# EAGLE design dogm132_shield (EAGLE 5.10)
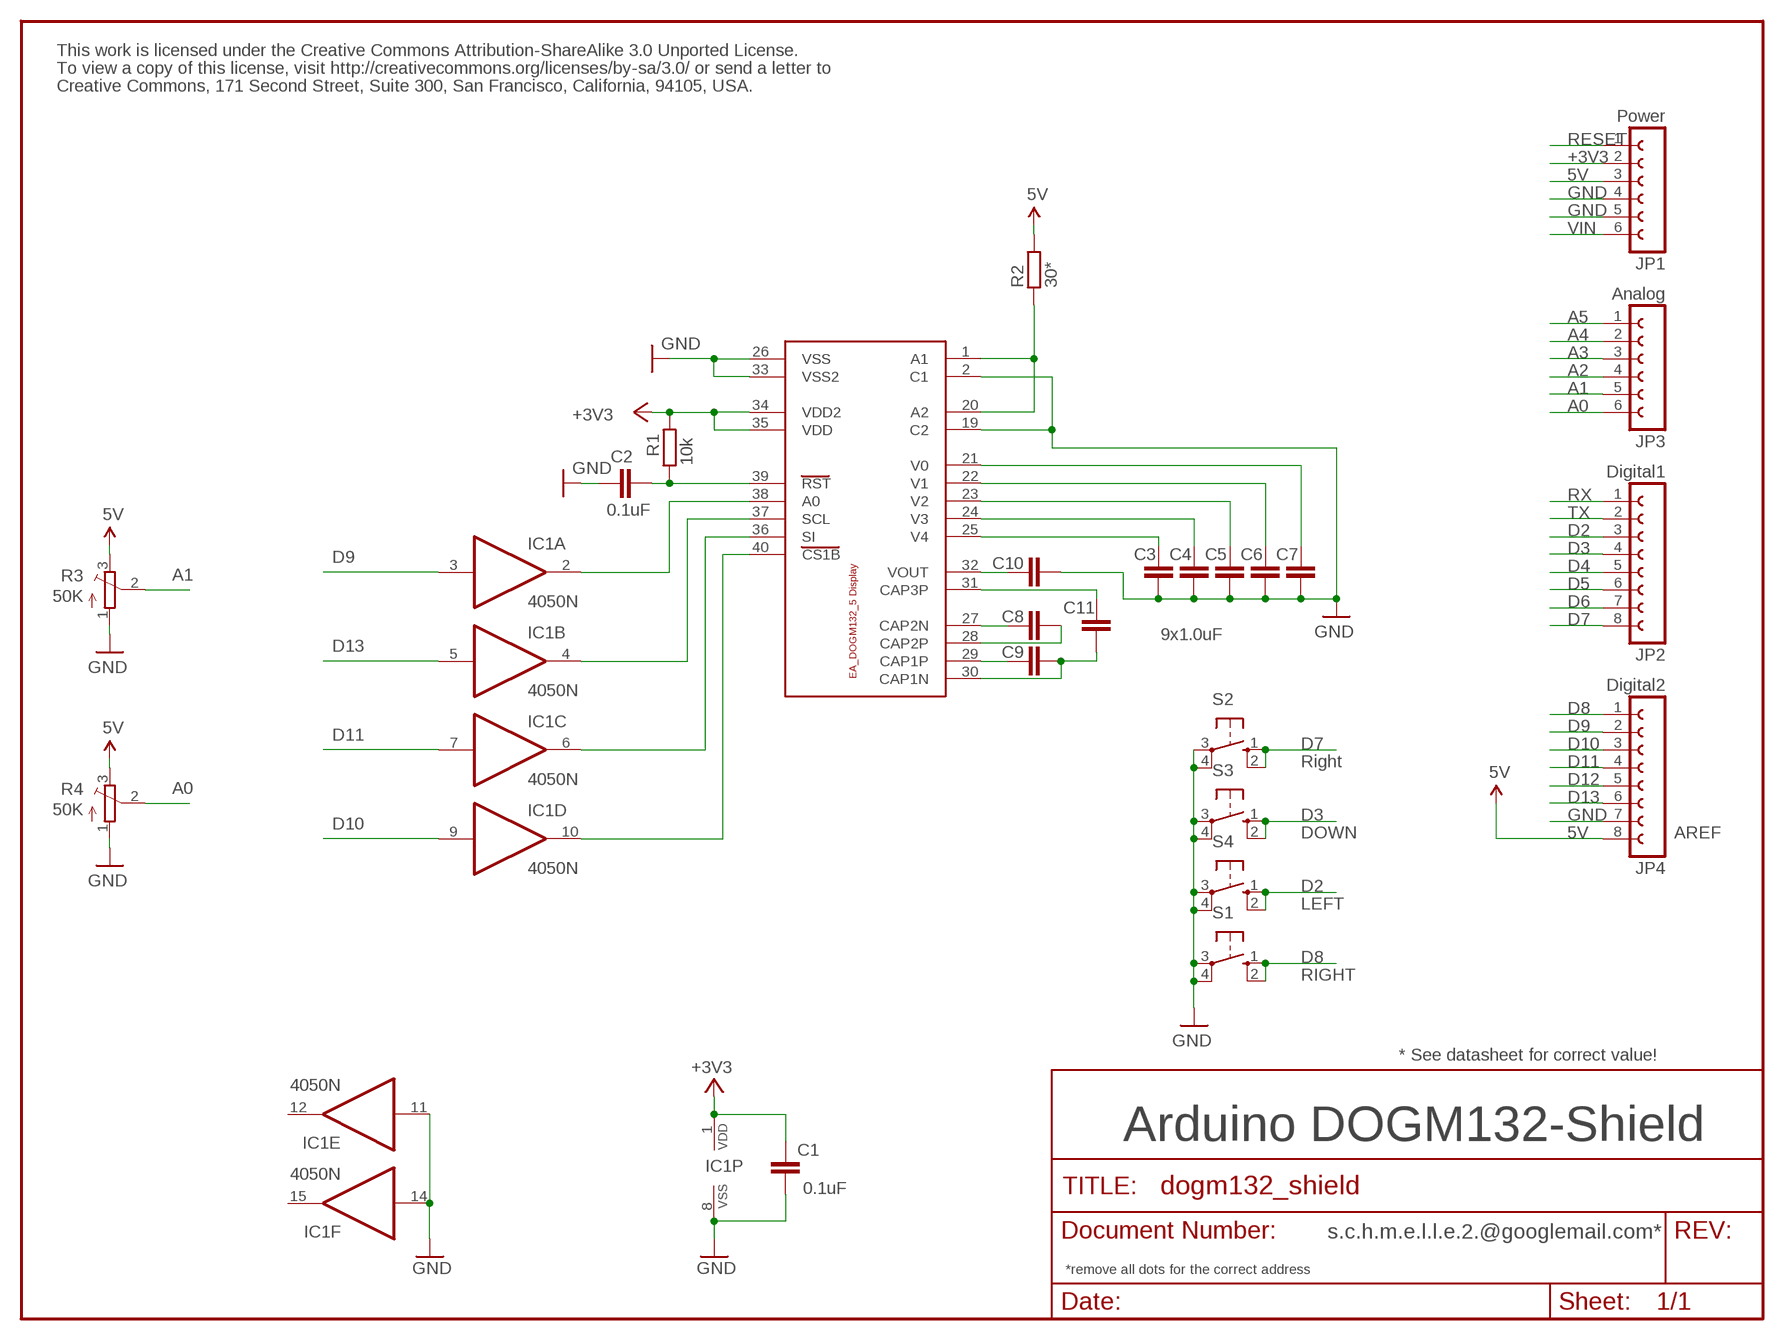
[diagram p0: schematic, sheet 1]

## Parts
C1  0.1uF  C-EU050-025X075  [C050-025X075]
C2  0.1uF  C-EU050-025X075  [C050-025X075]
C3  0.1uF  C-EU050-025X075  [C050-025X075]
C4  0.1uF  C-EU050-025X075  [C050-025X075]
C5  0.1uF  C-EU050-025X075  [C050-025X075]
C6  0.1uF  C-EU050-025X075  [C050-025X075]
C7  9x1.0uF  C-EU050-025X075  [C050-025X075]
C8  5x1.0uF  C-EU050-025X075  [C050-025X075]
C9  5x1.0uF  C-EU050-025X075  [C050-025X075]
C10  5x1.0uF  C-EU050-025X075  [C050-025X075]
C11  5x1.0uF  C-EU050-025X075  [C050-025X075]
IC1  4050N  [DIL16]
JP1  Power  FE06-1  [FE06]
JP2  Digital1  FE08-1  [FE08]
JP3  Analog  FE06-1  [FE06]
JP4  Digital2  FE08-1  [FE08]
R1  10k  R-EU_0207/10  [0207/10]
R2  30*  R-EU_0207/10  [0207/10]
R3  50K  R09K11  [ALPS_R09K11]
R4  50K  R09K11  [ALPS_R09K11]
S1  10-XX  [B3F-10XX]
S2  10-XX  [B3F-10XX]
S3  10-XX  [B3F-10XX]
S4  10-XX  [B3F-10XX]
U$1  EA_DOG-M_DISPLAY  [E_DOG-M_DISPLAY]

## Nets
5V [power]: JP1.3 JP4.8 R2.2 R3.3(E) R4.3(E)
+3V3: C1.2 IC1.1(P:VDD) JP1.2 R1.2 U$1.34(VDD2) U$1.35(VDD)
A0: JP3.6 R4.2(S)
A1: JP3.5 R3.2(S)
A2: JP3.4
A3: JP3.3
A4: JP3.2
A5: JP3.1
D2: JP2.3 S4.1(S) S4.2(S1)
D3: JP2.4 S3.1(S) S3.2(S1)
D4: JP2.5
D5: JP2.6
D6: JP2.7
D7: JP2.8 S2.1(S) S2.2(S1)
D8: JP4.1 S1.1(S) S1.2(S1)
D9: IC1.3(A:I) JP4.2
D10: IC1.9(D:I) JP4.3
D11: IC1.7(C:I) JP4.4
D12: JP4.5
D13: IC1.5(B:I) JP4.6
GND [power]: C1.1 C2.1 C3.1 C4.1 C5.1 C6.1 C7.1 C10.1 IC1.8(P:VSS) IC1.11(E:I) IC1.14(F:I) JP1.4 JP1.5 JP4.7 R3.1(A) R4.1(A) S1.3(P) S1.4(P1) S2.3(P) S2.4(P1) S3.3(P) S3.4(P1) S4.3(P) S4.4(P1) U$1.2(C1) U$1.19(C2) U$1.26(VSS) U$1.33(VSS2)
N$2: C2.2 R1.1 U$1.39(RST)
N$3: IC1.2(A:O) U$1.38(A0)
N$4: IC1.4(B:O) U$1.37(SCL)
N$5: IC1.6(C:O) U$1.36(SI)
N$6: IC1.10(D:O) U$1.40(CS1B)
N$7: R2.1 U$1.1(A1) U$1.20(A2)
N$8: C3.2 U$1.25(V4)
N$9: C4.2 U$1.24(V3)
N$10: C5.2 U$1.23(V2)
N$11: C6.2 U$1.22(V1)
N$12: C7.2 U$1.21(V0)
N$13: C11.2 U$1.31(CAP3P)
N$14: C8.2 U$1.27(CAP2N)
N$15: C8.1 U$1.28(CAP2P)
N$16: C9.2 U$1.29(CAP1P)
N$17: C9.1 C11.1 U$1.30(CAP1N)
N$18: C10.2 U$1.32(VOUT)
RESET: JP1.1
RX: JP2.1
TX: JP2.2
VIN [power]: JP1.6
Unconnected: IC1.12(E:O) IC1.15(F:O)

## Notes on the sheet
- This work is licensed under the Creative Commons Attribution-ShareAlike 3.0 Unported License.
- To view a copy of this license, visit http://creativecommons.org/licenses/by-sa/3.0/ or send a letter to
- Creative Commons, 171 Second Street, Suite 300, San Francisco, California, 94105, USA.
- Right
- DOWN | AREF
- LEFT
- RIGHT
- * See datasheet for correct value!
- Arduino DOGM132-Shield
- 0.1uF
- s.c.h.m.e.l.l.e.2.@googlemail.com*
- *remove all dots for the correct address

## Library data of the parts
C1-C11 = resistor:C-EU: CAPACITOR, European symbol
IC1 = 40xx:4050: Hex non-inverting BUFFER
JP1 JP3 = con-lsta:FE06-1: FEMALE HEADER
JP2 JP4 = con-lsta:FE08-1: FEMALE HEADER
R1 R2 = resistor:R-EU_: RESISTOR, European symbol
R3 R4 = pot-alps-r09k11:R09K11: ALPS R09K11x Potenziometer
S1-S4 = switch-omron:10-XX: OMRON SWITCH
U$1 = display_ea_dogm132:EA_DOG-M_DISPLAY

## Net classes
1 power: width 0.254 mm

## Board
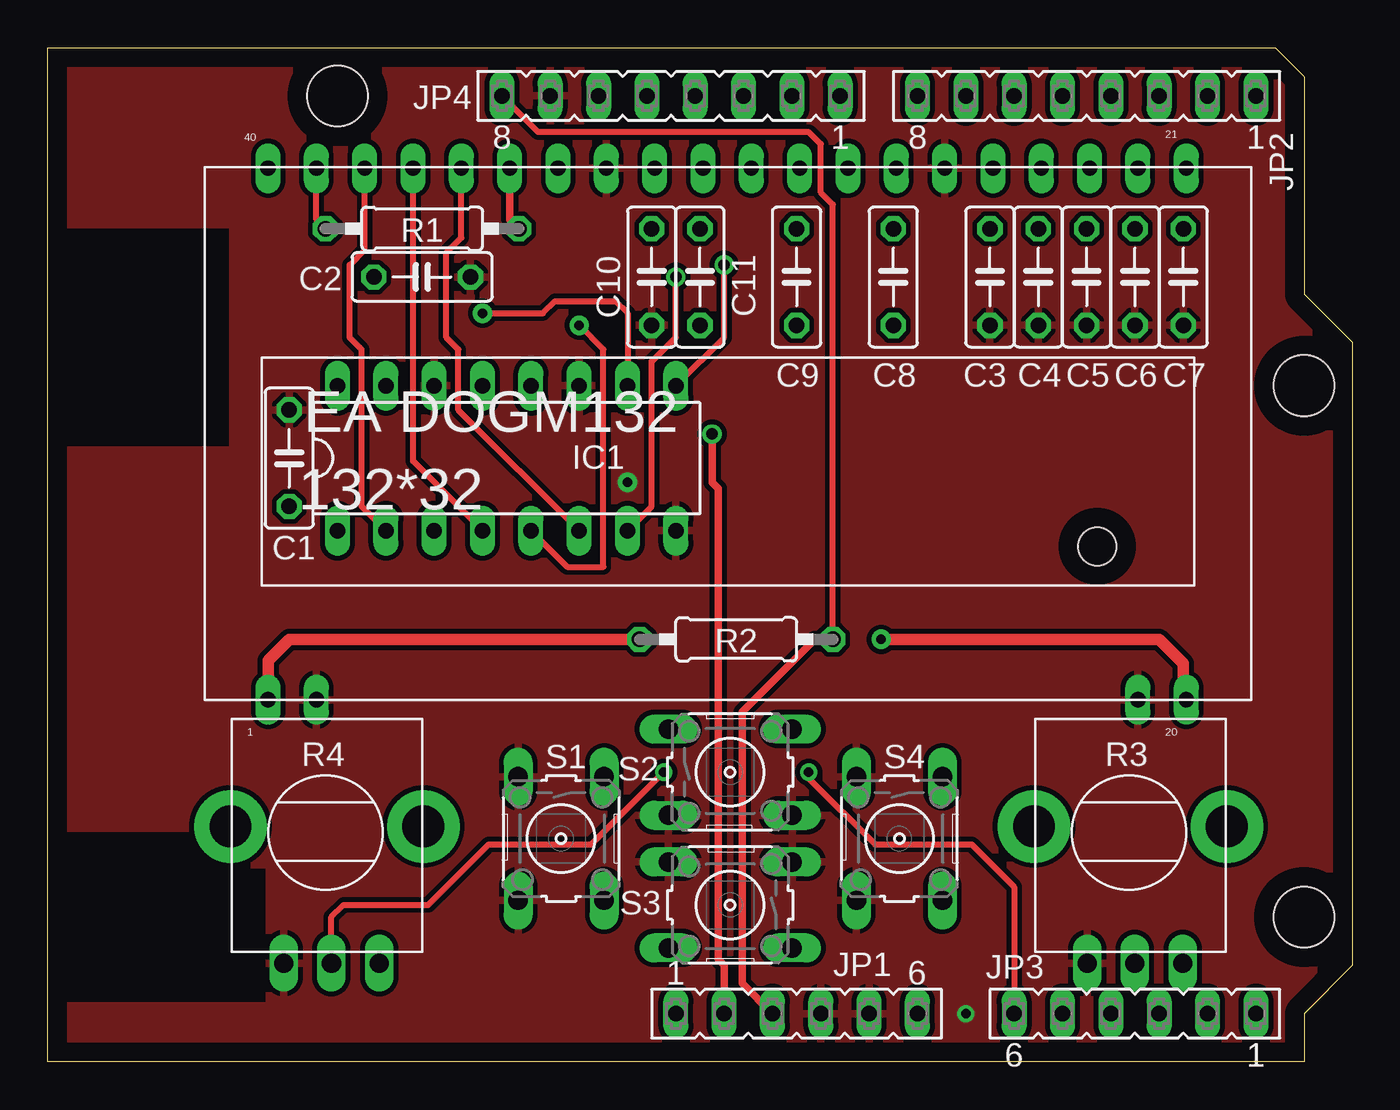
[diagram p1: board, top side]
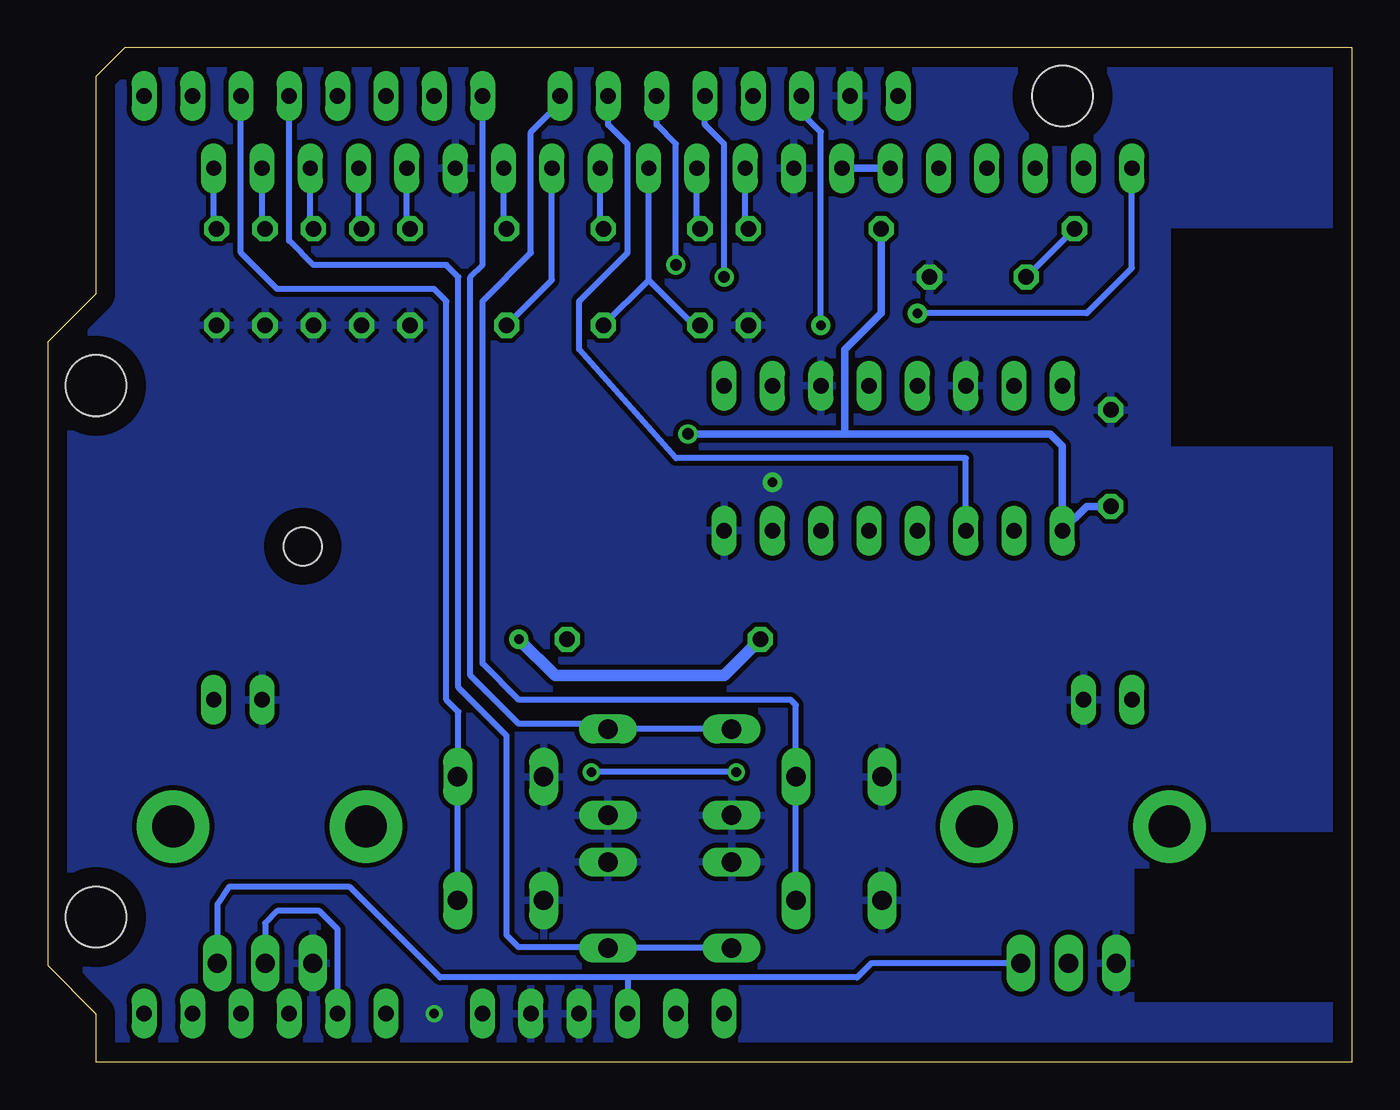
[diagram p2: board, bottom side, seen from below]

Size 68.58 x 53.34 mm. Coordinates in mm from the lower left corner, seen from the top.
Outline: 0,0 0,53.34 64.52,53.34 66.04,51.82 66.04,40.39 68.58,37.85 68.58,5.08 66.04,2.54 66.04,0 0,0
Copper layers (1*16): Top 0.035mm / dielectric 1.5mm / Bottom 0.035mm
Design rules "Bilex DRU": minimum track width 10mil, minimum drill 24mil, track to track 10mil, track to pad 10mil, pad to pad 10mil, via to via 10mil, smd to smd 10mil, copper to edge 40mil, drill to drill 8mil, minimum pad ring 10mil, minimum via ring 8mil, stop-mask expansion 4mil, vias tented up to drill 0mil, thermal gap 10mil
Holes 3.2 mm at 15.24,50.8 66.04,35.56 66.04,7.62
Holes 2 mm at 55.17,27.11
tKeepout: area 0,32.4 to 9.5,43.8; area 0,10.2 to 7.3,12.1; area 0,3.2 to 11.4,10.2
bKeepout: area 0,32.4 to 9.5,43.8; area 0,10.2 to 7.3,12.1; area 0,3.2 to 11.4,10.2
tRestrict: area 0,32.4 to 9.5,43.8; area 0,10.2 to 7.3,12.1; area 0,3.2 to 11.4,10.2
bRestrict: area 0,32.4 to 9.5,43.8; area 0,10.2 to 7.3,12.1; area 0,3.2 to 11.4,10.2

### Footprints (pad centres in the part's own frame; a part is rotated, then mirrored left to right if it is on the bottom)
C050-025X075 = drill 0.813 octagon: 1 -2.54,0; 2 2.54,0
DIL16 = drill 0.813 long: 1 -8.89,-3.81; 2 -6.35,-3.81; 3 -3.81,-3.81; 4 -1.27,-3.81; 5 1.27,-3.81; 6 3.81,-3.81; 7 6.35,-3.81; 8 8.89,-3.81; 9 8.89,3.81; 10 6.35,3.81; 11 3.81,3.81; 12 1.27,3.81; 13 -1.27,3.81; 14 -3.81,3.81; 15 -6.35,3.81; 16 -8.89,3.81
FE06 = drill 0.813 long: 1 -6.35,0; 2 -3.81,0; 3 -1.27,0; 4 1.27,0; 5 3.81,0; 6 6.35,0
FE08 = drill 0.813 long: 1 -8.89,0; 2 -6.35,0; 3 -3.81,0; 4 -1.27,0; 5 1.27,0; 6 3.81,0; 7 6.35,0; 8 8.89,0
0207/10 = drill 0.813 octagon: 1 -5.08,0; 2 5.08,0
ALPS_R09K11 = drill 1 long: 1 -2.183,-7.183; 2 0.318,-7.183; 3 2.817,-7.183 | drill 2.2 pad 3.81 round: N$1 -4.989,0; N$2 5.147,0
B3F-10XX = drill 1.016 long: 1 -3.251,2.261; 2 3.251,2.261; 3 -3.251,-2.261; 4 3.251,-2.261
E_DOG-M_DISPLAY = drill 0.8 long: 1 3.334,0; 2 5.874,0; 19 49.054,0; 20 51.594,0; 21 51.594,27.94; 22 49.054,27.94; 23 46.514,27.94; 24 43.974,27.94; 25 41.434,27.94; 26 38.894,27.94; 27 36.354,27.94; 28 33.814,27.94; 29 31.274,27.94; 30 28.734,27.94; 31 26.194,27.94; 32 23.654,27.94; 33 21.114,27.94; 34 18.574,27.94; 35 16.034,27.94; 36 13.494,27.94; 37 10.954,27.94; 38 8.414,27.94; 39 5.874,27.94; 40 3.334,27.94

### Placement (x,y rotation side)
C1  12.7,31.75 270 top
C2  19.68,41.27 180 top
C3  49.53,41.27 90 top
C4  52.07,41.27 90 top
C5  54.61,41.27 90 top
C6  57.15,41.27 90 top
C7  59.69,41.27 90 top
C8  44.45,41.27 90 top
C9  39.37,41.27 90 top
C10  31.75,41.27 90 top
C11  34.29,41.27 90 top
IC1  24.13,31.75 0 top
JP1  39.37,2.54 0 top
JP2  54.61,50.8 180 top
JP3  57.15,2.54 180 top
JP4  32.77,50.8 180 top
R1  19.68,43.81 0 top
R2  36.2,22.23 0 top
R3  56.83,12.38 0 top
R4  14.61,12.38 0 top
S1  26.99,11.75 270 top
S2  35.88,15.24 0 top
S3  35.88,8.26 180 top
S4  44.77,11.75 270 top
U$1  8.26,19.05 0 top

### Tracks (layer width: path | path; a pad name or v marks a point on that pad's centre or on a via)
5V
  Top 0.305: JP4.8 25.78,48.9 40.01,48.9 40.64,48.26 40.64,45.72 41.27,45.09 R2.2
  Top 0.406: JP1.3 36.51,4.13 36.51,18.41 40.32,22.23 R2.2
  Bottom 0.305: 38.1,4.45 JP1.3 | 38.1,4.45 26.04,4.45 25.28,5.2 R4.3 | R3.3 59.65,8.29 59.05,9.21 52.7,9.21 47.94,4.45 38.1,4.45
+3V3  (via drill 0.6 pad 1.02)
  Top 0.406: R1.2 24.29,44.29 U$1.35 | v34.92,33.02 34.92,30.48 35.24,30.16 35.24,5.4 35.56,5.08 JP1.2
  Bottom 0.406: C1.2 13.97,29.21 IC1.1 15.24,32.38 15.88,33.02 26.67,33.02 | R1.2 24.77,39.37 26.67,37.47 26.67,33.02 | U$1.35 U$1.34 | v34.92,33.02 26.67,33.02
A0  (via drill 0.5)
  Top 0.305: R4.2 14.92,7.62 15.56,8.26 20,8.26 23.18,11.43 28.57,11.43 v32.38,15.24 | v40.01,15.24 40.01,14.92 43.5,11.43 48.58,11.43 50.8,9.21 JP3.6
  Bottom 0.305: v32.38,15.24 v40.01,15.24
A1
  Bottom 0.305: R3.2 57.15,7.3 56.52,7.94 54.29,7.94 53.34,6.99 JP3.5
D2
  Bottom 0.305: JP2.3 58.42,42.55 56.52,40.64 48.26,40.64 47.62,40.01 47.62,19.05 46.99,18.41 46.99,16.31 S4.1 S4.2
D3
  Bottom 0.305: JP2.4 55.88,43.18 54.61,41.91 47.62,41.91 46.99,41.27 46.99,19.68 44.45,17.14 44.45,6.67 43.81,6.03 39.17,6.03 S3.1 S3.2
D7
  Bottom 0.305: JP2.8 45.72,41.91 46.35,41.27 46.35,20.32 43.81,17.78 39.73,17.78 S2.2 S2.1
D8
  Bottom 0.305: JP4.1 41.66,50.42 43.18,48.9 43.18,42.55 45.72,40.01 45.72,20.95 43.81,19.05 29.53,19.05 29.25,18.77 S1.1 S1.2
D9
  Bottom 0.305: JP4.2 39.12,49.28 38.1,48.26 38.1,42.55 40.64,40.01 40.64,37.47 35.56,31.75 20.32,31.75 IC1.3
D10  (via drill 0.6)
  Top 0.305: v35.56,41.91 35.56,38.1 IC1.9
  Bottom 0.305: JP4.3 36.58,49.28 35.56,48.26 v35.56,41.91
D11  (via drill 0.6)
  Top 0.305: v33.02,41.27 33.02,38.1 31.75,36.83 31.75,29.21 IC1.7
  Bottom 0.305: JP4.4 34.04,49.28 33.02,48.26 v33.02,41.27
D13  (via drill 0.5 pad 1.02)
  Top 0.305: v27.94,38.73 29.21,37.47 29.21,26.04 27.3,26.04 IC1.5
  Bottom 0.305: JP4.6 28.96,49.91 27.94,48.9 v27.94,38.73
GND  (via drill 0.5, 0.5 pad 1.02)
  other vias: 30.48,30.48 48.26,2.54
  pour Top: 0,0 0,53.34 64.52,53.34 66.04,51.82 66.04,40.39 68.58,37.85 68.58,5.08 66.04,2.54 66.04,0
  pour Bottom: 0,0 0,53.34 64.52,53.34 66.04,51.82 66.04,40.39 68.58,37.85 68.58,5.08 66.04,2.54 66.04,0
N$2
  Top 0.305: R1.1 14.13,44.29 U$1.39
  Bottom 0.305: R1.1 C2.2
N$3
  Top 0.305: U$1.38 16.67,42.7 15.88,41.91 15.88,38.1 16.51,37.47 16.51,29.21 IC1.2
N$4
  Top 0.305: U$1.37 19.21,31.59 IC1.4
N$5
  Top 0.305: U$1.36 21.75,43.34 20.95,42.55 20.95,38.1 21.59,37.47 21.59,34.29 IC1.6
N$6  (via drill 0.5 pad 1.02)
  Top 0.305: v22.86,39.37 26.04,39.37 26.67,40.01 29.84,40.01 30.48,39.37 IC1.10
  Bottom 0.305: U$1.40 11.59,41.75 13.97,39.37 v22.86,39.37
N$7  (via drill 0.5 pad 1.02)
  Top 0.61: U$1.1 11.59,21.11 12.7,22.23 R2.1 | 59.69,19.21 59.69,20.95 58.42,22.23 v43.81,22.23
  Top 0.813: 59.69,19.21 U$1.20
  Bottom 0.61: R2.1 33.02,20.32 41.91,20.32 v43.81,22.23
N$8
  Bottom 0.305: U$1.25 49.69,43.97 C3.2
N$9
  Bottom 0.305: U$1.24 52.23,43.97 C4.2
N$10
  Bottom 0.305: U$1.23 54.77,43.97 C5.2
N$11
  Bottom 0.305: U$1.22 57.31,43.97 C6.2
N$12
  Bottom 0.305: U$1.21 59.85,43.97 C7.2
N$13
  Bottom 0.305: U$1.31 34.45,43.97 C11.2
N$14
  Bottom 0.305: U$1.27 44.61,43.97 C8.2
N$15
  Bottom 0.305: U$1.28 42.07,41.12 C8.1
N$16
  Bottom 0.305: U$1.29 39.53,43.97 C9.2
N$17
  Bottom 0.305: 36.99,41.12 U$1.30 | 36.99,41.12 C9.1 | 34.61,38.73 36.99,41.12
  Bottom 0.406: C11.1 34.61,38.73
N$18
  Bottom 0.305: U$1.32 31.91,43.97 C10.2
